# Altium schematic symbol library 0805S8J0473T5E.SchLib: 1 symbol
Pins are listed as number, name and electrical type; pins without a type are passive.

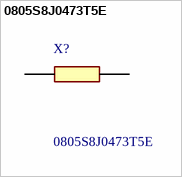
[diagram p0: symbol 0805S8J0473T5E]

## 0805S8J0473T5E
designator X?
Thick Film Resistors - SMD RMC 0805 1/8W-S 5% T/R-5000; Manufacturer_Name: ROYALOHM; Geometry.Height: 0.65mm
footprint RESC2013X65N
pins: 1, 2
